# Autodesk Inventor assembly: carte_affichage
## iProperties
Created: 2011-01
Part Number: carte_affichage
Document SubType Name: Assembly
Designer: eric
Mass: 32.9753 g
Surface Area: 220.66 cm^2
Volume: 32.9753 cm^3
Density: 1 g/cm^3
Norme de conversion: IGES 5.3
Nom du fichier: No Iges File Name specified
Préprocesseur: Autodesk Inventor 2011
Postprocesseur: Build: 342, Release: 2008 SP3 - Date: Tue 05/27/2008
Unités envoyées: MM
Incertitude: 0.01
Author: eric
